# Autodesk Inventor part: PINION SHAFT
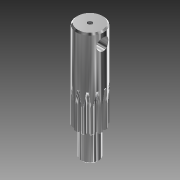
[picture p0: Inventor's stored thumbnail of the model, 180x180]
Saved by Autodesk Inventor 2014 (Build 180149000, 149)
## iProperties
Shininess: 64.0
Length Units: 11269
Angle Units: 11279
Time Units: 11290
Mass Units: 11283
Length Display Precision: 3
Angle Display Precision: 2
Compacted: True
Part Number: PINION SHAFT
Document SubType Name: Modeling
Created: 2003-10
Designer: Autodesk, Inc.
Manufacturer: Standard
Standards Organization: Custom
Mass: 506.446 g
Surface Area: 152.229 cm^2
Volume: 64.5977 cm^3
Density: 7.84 g/cm^3
Material: Steel, High Strength Low Alloy
Appearance: Chrome - Polished
Density: 0.0
Volumn: 0.0
Area: 0.0
PropertySet Name: Model Information
Control State: 0
Master: False
Checked Out: False
Author: Autodesk, Inc.
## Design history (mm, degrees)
sketch "Sketch1" dims "d4" = 6.7945 (= Big_R), "d5" = 5.54567 (= 2 x little_r)
  geometry: L1 (0, 12.7)-(5.815, 12.7); L2 (5.815, 12.7)-(5.815, 14.817); L3 (5.815, 14.817)-(0, 14.817); L4 (0, 14.817)-(0, 12.7); L5 (-8.163, 9.729)-(5.815, 14.817); L6 (0, 0)-(0, 10.251); L7 (0, 11.934)-(0, 12.7); L8 (0, 11.934)-(0, 10.251); L9 (-0.191, 11.933)-(-0.184, 10.731); L10 (-0.181, 10.249)-(0, 0); L11 (0, 0)-(1.934, 14.69); L12 (0, 0)-(-1.338, 10.163); L13 (0, 0)-(3.923, 9.471); L14 (3.273, 11.477)-(2.955, 10.318); L15 (-0.181, 10.249)-(-0.184, 10.731); A1 r 12.7 centre (0, 0) between (0, 12.7) and (-8.163, 9.729); A2 r 14.817 centre (0, 0) between (0, 14.817) and (1.934, 14.69); A3 r 11.934 centre (0, 0) between (0, 11.934) and (6.294, 10.14); A4 r 10.251 centre (0, 0) between (0, 10.251) and (-0.181, 10.249); A5 r 6.795 centre (6.294, 10.14) between (1.365, 14.817) and (0, 12.7); A6 r 2.773 centre (2.568, 11.654) between (0, 12.7) and (-0.191, 11.933); A7 r 10.251 centre (0, 0) between (-0.651, 10.23) and (-1.338, 10.163); A8 r 0.498 centre (-0.682, 10.728) between (-0.651, 10.23) and (-0.184, 10.731); A9 r 10.251 centre (0, 0) between (3.923, 9.471) and (3.276, 9.713); A10 r 0.498 centre (3.435, 10.186) between (2.955, 10.318) and (3.276, 9.713); A11 r 2.773 centre (0.536, 11.922) between (3.273, 11.477) and (3.287, 12.267); A12 r 6.795 centre (-3.455, 11.423) between (3.287, 12.267) and (2.516, 14.665); A13 r 14.879 centre (0, 0) between (2.516, 14.665) and (1.365, 14.817); 2 further points
  constraints: 30 point on circle, 29 end point, 13 centre point, 9 coincident, 9 symmetric about line, 4 tangent, 3 collinear, 3 point on line, 2 parallel, 2 vertical, 1 horizontal, 1 perpendicular, 12 other
  dimensions: "d0" = 25.4 diameter of A1 (= Pitch_Diameter); "d1" = 2.11667 distance of L1.end L2.end (= Addendum); "d2" = 20 deg angle of L1 L5 (= Tooth_Form); "d3" = 4.56565 distance of L6.end L3.end (= Whole_Depth); "d6" = 7.5 deg angle of L11 L6 (= mirror_angle); "d7" = 7.5 deg angle of L12 L6 (= mirror_angle); "d8" = 0.49848 radius of A8 (= Root_Fillet)
extrude "Extrusion1" new body sketch "Sketch1" distance "d9" = 25.4; taper "d10" = 0 deg
pattern_circular "Circular Pattern1" dims angle "d13" = 360 deg
sketch "Sketch2"
  geometry: C1 r 14.879 at (0, 0); 1 further point
  constraints: 1 centre point, 1 coincident
  dimensions: "d14" = 29.758 diameter of C1
extrude "Extrusion2" join sketch "Sketch2" distance "d15" = 71.4502; taper "d16" = 0 deg
sketch "Sketch3"
  geometry: C1 r 9.5 at (0, 0); 1 further point
  constraints: 1 centre point, 1 coincident
  dimensions: "d17" = 18.9992 diameter of C1
extrude "Extrusion3" join sketch "Sketch3" distance "d18" = 30.1498; taper "d19" = 0 deg
chamfer "Chamfer1" distance "d20" = 1.5875; stored, may be unused: second distance "d21" = 2, angle "d67" = 45 deg
chamfer "Chamfer2" distance "d22" = 1.5875; stored, may be unused: second distance "d23" = 2, angle "d68" = 45 deg
workplane "Work Plane2"
sketch "Sketch4"
  geometry: L1 (-13.292, 96.85)-(13.292, 96.85) reference; L2 (0, 96.85)-(0, 65.832); C1 r 6.54 at (0, 84.15)
  constraints: 2 end point, 1 centre point, 1 midpoint, 1 perpendicular, 1 point on line
  dimensions: "d26" = 13.081 diameter of C1; "d27" = 12.7 distance from line of L1 C1.centre
extrude "Extrusion4" cut sketch "Sketch4" distance "d28" = 50.8; taper "d29" = 0 deg
workplane "Work Plane3"
sketch "Sketch10"
  geometry: L1 (-5.206, 9.385)-(-5.801, 10.429) reference; L2 (-3.273, 11.477)-(-2.955, 10.318) reference; L3 (-5.801, 10.429)-(-5.206, 9.385); L4 (-2.955, 10.318)-(-3.273, 11.477); L5 (-30.301, 30.745)-(3.482, 44.738); L6 (-8.59, 12.149)-(-2.517, 14.665); L7 (0.184, 10.731)-(0.191, 11.933) reference; L8 (2.904, 11.575)-(2.6, 10.413) reference; L9 (0.191, 11.933)-(0.184, 10.731); L10 (2.904, 11.575)-(2.6, 10.413); L11 (5.524, 9.201)-(6.131, 10.239) reference; L12 (8.303, 8.572)-(7.458, 7.718) reference; L13 (5.524, 9.201)-(6.131, 10.239); L14 (7.458, 7.718)-(8.303, 8.572); L15 (9.385, 5.206)-(10.429, 5.801) reference; L16 (11.477, 3.273)-(10.318, 2.955) reference; L17 (9.385, 5.206)-(10.429, 5.801); L18 (11.477, 3.273)-(10.318, 2.955); A1 r 6.795 centre (3.455, 11.423) between (-2.517, 14.665) and (-3.287, 12.267) reference; A2 r 14.879 centre (0, 0) between (-2.517, 14.665) and (-8.59, 12.149) reference; A3 r 6.795 centre (-10.52, 5.634) between (-6.35, 10.999) and (-8.59, 12.149) reference; A4 r 2.773 centre (-8.051, 8.809) between (-5.801, 10.429) and (-6.35, 10.999) reference; A5 r 0.498 centre (-4.773, 9.632) between (-5.206, 9.385) and (-4.552, 9.185) reference; A6 r 10.251 centre (0, 0) between (-3.276, 9.713) and (-4.552, 9.185) reference; A7 r 0.498 centre (-3.435, 10.186) between (-3.276, 9.713) and (-2.955, 10.318) reference; A8 r 2.773 centre (-0.536, 11.922) between (-3.287, 12.267) and (-3.273, 11.477) reference; A9 r 14.879 centre (0, 0) between (-2.517, 14.665) and (-8.59, 12.149); A10 r 6.795 centre (-10.52, 5.634) between (-6.35, 10.999) and (-8.59, 12.149); A11 r 2.773 centre (-8.051, 8.809) between (-5.801, 10.429) and (-6.35, 10.999); A12 r 0.498 centre (-4.773, 9.632) between (-5.206, 9.385) and (-4.552, 9.185); A13 r 10.251 centre (0, 0) between (-3.276, 9.713) and (-4.552, 9.185); A14 r 6.795 centre (3.455, 11.423) between (-2.517, 14.665) and (-3.287, 12.267); A15 r 2.773 centre (-0.536, 11.922) between (-3.287, 12.267) and (-3.273, 11.477); A16 r 0.498 centre (-3.435, 10.186) between (-3.276, 9.713) and (-2.955, 10.318); A17 r 10.251 centre (0, 0) between (-3.276, 9.713) and (-4.552, 9.185) reference; A18 r 6.795 centre (8.704, 8.165) between (5.153, 13.958) and (3.287, 12.267) reference; A19 r 14.879 centre (0, 0) between (5.153, 13.958) and (-1.365, 14.816) reference; A20 r 6.795 centre (-6.294, 10.14) between (0, 12.7) and (-1.365, 14.816) reference; A21 r 2.773 centre (-2.568, 11.654) between (0.191, 11.933) and (0, 12.7) reference; A22 r 0.498 centre (0.682, 10.728) between (0.184, 10.731) and (0.651, 10.23) reference; A23 r 10.251 centre (0, 0) between (2.019, 10.05) and (0.651, 10.23) reference; A24 r 0.498 centre (2.118, 10.539) between (2.019, 10.05) and (2.6, 10.413) reference; A25 r 2.773 centre (5.497, 10.593) between (3.287, 12.267) and (2.904, 11.575) reference; A26 r 6.795 centre (-6.294, 10.14) between (0, 12.7) and (-1.365, 14.816); A27 r 2.773 centre (-2.568, 11.654) between (0.191, 11.933) and (0, 12.7); A28 r 0.498 centre (0.682, 10.728) between (0.184, 10.731) and (0.651, 10.23); A29 r 0.498 centre (2.118, 10.539) between (2.019, 10.05) and (2.6, 10.413); A30 r 2.773 centre (5.497, 10.593) between (3.287, 12.267) and (2.904, 11.575); A31 r 6.795 centre (8.704, 8.165) between (5.153, 13.958) and (3.287, 12.267); A32 r 14.879 centre (0, 0) between (5.153, 13.958) and (-1.365, 14.816); A33 r 10.251 centre (0, 0) between (2.019, 10.05) and (0.651, 10.23); A34 r 6.795 centre (11.62, 2.72) between (11.442, 9.512) and (8.98, 8.98) reference; A35 r 14.879 centre (0, 0) between (11.442, 9.512) and (6.226, 13.514) reference; A36 r 6.795 centre (-0.381, 11.928) between (6.35, 10.999) and (6.226, 13.514) reference; A37 r 2.773 centre (3.603, 11.377) between (6.131, 10.239) and (6.35, 10.999) reference; A38 r 0.498 centre (5.955, 8.949) between (5.524, 9.201) and (5.679, 8.534) reference; A39 r 10.251 centre (0, 0) between (6.774, 7.694) and (5.679, 8.534) reference; A40 r 0.498 centre (7.103, 8.068) between (6.774, 7.694) and (7.458, 7.718) reference; A41 r 2.773 centre (10.057, 6.425) between (8.98, 8.98) and (8.303, 8.572) reference; A42 r 14.879 centre (0, 0) between (11.442, 9.512) and (6.226, 13.514); A43 r 6.795 centre (-0.381, 11.928) between (6.35, 10.999) and (6.226, 13.514); A44 r 2.773 centre (3.603, 11.377) between (6.131, 10.239) and (6.35, 10.999); A45 r 0.498 centre (5.955, 8.949) between (5.524, 9.201) and (5.679, 8.534); A46 r 0.498 centre (7.103, 8.068) between (6.774, 7.694) and (7.458, 7.718); A47 r 2.773 centre (10.057, 6.425) between (8.98, 8.98) and (8.303, 8.572); A48 r 6.795 centre (11.62, 2.72) between (11.442, 9.512) and (8.98, 8.98); A49 r 10.251 centre (0, 0) between (6.774, 7.694) and (5.679, 8.534); A50 r 6.795 centre (11.423, -3.455) between (14.665, 2.517) and (12.267, 3.287) reference; A51 r 14.879 centre (0, 0) between (14.665, 2.517) and (12.149, 8.59) reference; A52 r 6.795 centre (5.634, 10.52) between (10.999, 6.35) and (12.149, 8.59) reference; A53 r 2.773 centre (8.809, 8.051) between (10.429, 5.801) and (10.999, 6.35) reference; A54 r 0.498 centre (9.632, 4.773) between (9.385, 5.206) and (9.185, 4.552) reference; A55 r 10.251 centre (0, 0) between (9.713, 3.276) and (9.185, 4.552) reference; A56 r 0.498 centre (10.186, 3.435) between (9.713, 3.276) and (10.318, 2.955) reference; A57 r 2.773 centre (11.922, 0.536) between (12.267, 3.287) and (11.477, 3.273) reference; A58 r 10.251 centre (0, 0) between (9.713, 3.276) and (9.185, 4.552); A59 r 0.498 centre (9.632, 4.773) between (9.385, 5.206) and (9.185, 4.552); A60 r 0.498 centre (10.186, 3.435) between (9.713, 3.276) and (10.318, 2.955); A61 r 2.773 centre (11.922, 0.536) between (12.267, 3.287) and (11.477, 3.273); A62 r 2.773 centre (8.809, 8.051) between (10.429, 5.801) and (10.999, 6.35); A63 r 6.795 centre (5.634, 10.52) between (10.999, 6.35) and (12.149, 8.59); A64 r 6.794 centre (11.423, -3.455) between (14.665, 2.517) and (12.267, 3.287)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
  constraints: 66 point on circle, 32 centre point, 30 concentric, 27 tangent, 20 end point, 8 collinear, 1 parallel
  dimensions: "d32" = 40 distance from line of L5 A17.centre
revolve "Revolution1" sketch "Sketch10" stored, may be unused: angle "d33" = 90 deg
sketch "Sketch11"
  geometry: L1 (0.184, 10.731)-(0.191, 11.933) reference; L2 (2.904, 11.575)-(2.6, 10.413) reference; L3 (0.184, 10.731)-(0.191, 11.933); L4 (2.6, 10.413)-(2.904, 11.575); L5 (-8.56, 41.472)-(25.088, 37.042); L6 (-1.365, 14.816)-(5.153, 13.958); C1 r 7.912 at (0, 0) reference; A1 r 6.795 centre (8.704, 8.165) between (5.153, 13.958) and (3.287, 12.267) reference; A2 r 14.879 centre (0, 0) between (5.153, 13.958) and (-1.365, 14.816) reference; A3 r 6.795 centre (-6.294, 10.14) between (0, 12.7) and (-1.365, 14.816) reference; A4 r 2.773 centre (-2.568, 11.654) between (0.191, 11.933) and (0, 12.7) reference; A5 r 0.498 centre (0.682, 10.728) between (0.184, 10.731) and (0.651, 10.23) reference; A6 r 10.251 centre (0, 0) between (2.019, 10.05) and (0.651, 10.23) reference; A7 r 0.498 centre (2.118, 10.539) between (2.019, 10.05) and (2.6, 10.413) reference; A8 r 2.773 centre (5.497, 10.593) between (3.287, 12.267) and (2.904, 11.575) reference; A9 r 14.879 centre (0, 0) between (5.153, 13.958) and (-1.365, 14.816); A10 r 6.795 centre (-6.294, 10.14) between (0, 12.7) and (-1.365, 14.816); A11 r 2.773 centre (-2.568, 11.654) between (0.191, 11.933) and (0, 12.7); A12 r 0.498 centre (0.682, 10.728) between (0.184, 10.731) and (0.651, 10.23); A13 r 10.251 centre (0, 0) between (2.019, 10.05) and (0.651, 10.23); A14 r 6.795 centre (8.704, 8.165) between (5.153, 13.958) and (3.287, 12.267); A15 r 2.773 centre (5.497, 10.593) between (3.287, 12.267) and (2.904, 11.575); A16 r 0.498 centre (2.118, 10.539) between (2.019, 10.05) and (2.6, 10.413)
  constraints: 16 point on circle, 8 centre point, 8 end point, 8 tangent, 6 concentric, 2 collinear, 1 parallel
  dimensions: "d35" = 40 distance from line of C1.centre L5
revolve "Revolution2" sketch "Sketch11" stored, may be unused: angle "d36" = 90 deg
sketch "Sketch12"
  geometry: L1 (5.524, 9.201)-(6.131, 10.239) reference; L2 (8.303, 8.572)-(7.458, 7.718) reference; L3 (8.303, 8.572)-(7.458, 7.718); L4 (5.524, 9.201)-(6.131, 10.239); L5 (37.465, 21.671)-(7.155, 44.928); L6 (11.442, 9.512)-(6.226, 13.514); C1 r 7.912 at (0, 0) reference; A1 r 6.795 centre (11.62, 2.72) between (11.442, 9.512) and (8.98, 8.98) reference; A2 r 14.879 centre (0, 0) between (11.442, 9.512) and (6.226, 13.514) reference; A3 r 6.795 centre (-0.381, 11.928) between (6.35, 10.999) and (6.226, 13.514) reference; A4 r 2.773 centre (3.603, 11.377) between (6.131, 10.239) and (6.35, 10.999) reference; A5 r 0.498 centre (5.955, 8.949) between (5.524, 9.201) and (5.679, 8.534) reference; A6 r 10.251 centre (0, 0) between (6.774, 7.694) and (5.679, 8.534) reference; A7 r 0.498 centre (7.103, 8.068) between (6.774, 7.694) and (7.458, 7.718) reference; A8 r 2.773 centre (10.057, 6.425) between (8.98, 8.98) and (8.303, 8.572) reference; A9 r 14.879 centre (0, 0) between (11.442, 9.512) and (6.226, 13.514); A10 r 0.498 centre (5.955, 8.949) between (5.524, 9.201) and (5.679, 8.534); A11 r 6.795 centre (-0.381, 11.928) between (6.35, 10.999) and (6.226, 13.514); A12 r 2.773 centre (3.603, 11.377) between (6.131, 10.239) and (6.35, 10.999); A13 r 0.498 centre (7.103, 8.068) between (6.774, 7.694) and (7.458, 7.718); A14 r 2.773 centre (10.057, 6.425) between (8.98, 8.98) and (8.303, 8.572); A15 r 6.795 centre (11.62, 2.72) between (11.442, 9.512) and (8.98, 8.98); A16 r 10.251 centre (0, 0) between (6.774, 7.694) and (5.679, 8.534)
  constraints: 16 point on circle, 8 centre point, 8 end point, 7 concentric, 7 tangent, 2 collinear, 1 parallel
  dimensions: "d37" = 40 distance from line of C1.centre L5
revolve "Revolution3" sketch "Sketch12" stored, may be unused: angle "d38" = 90 deg
sketch "Sketch13"
  geometry: L1 (9.385, 5.206)-(10.429, 5.801) reference; L2 (11.477, 3.273)-(10.318, 2.955) reference; L3 (9.385, 5.206)-(10.429, 5.801); L4 (10.318, 2.955)-(11.477, 3.273); L5 (14.665, 2.517)-(12.149, 8.59); L6 (43.302, -0.015)-(26.182, 41.316); C1 r 7.912 at (0, 0) reference; A1 r 6.795 centre (11.423, -3.455) between (14.665, 2.517) and (12.267, 3.287) reference; A2 r 14.879 centre (0, 0) between (14.665, 2.517) and (12.149, 8.59) reference; A3 r 6.795 centre (5.634, 10.52) between (10.999, 6.35) and (12.149, 8.59) reference; A4 r 2.773 centre (8.809, 8.051) between (10.429, 5.801) and (10.999, 6.35) reference; A5 r 0.498 centre (9.632, 4.773) between (9.385, 5.206) and (9.185, 4.552) reference; A6 r 10.251 centre (0, 0) between (9.713, 3.276) and (9.185, 4.552) reference; A7 r 0.498 centre (10.186, 3.435) between (9.713, 3.276) and (10.318, 2.955) reference; A8 r 2.773 centre (11.922, 0.536) between (12.267, 3.287) and (11.477, 3.273) reference; A9 r 6.795 centre (5.634, 10.52) between (10.999, 6.35) and (12.149, 8.59); A10 r 2.773 centre (8.809, 8.051) between (10.429, 5.801) and (10.999, 6.35); A11 r 0.498 centre (9.632, 4.773) between (9.385, 5.206) and (9.185, 4.552); A12 r 0.498 centre (10.186, 3.435) between (9.713, 3.276) and (10.318, 2.955); A13 r 2.773 centre (11.922, 0.536) between (12.267, 3.287) and (11.477, 3.273); A14 r 10.251 centre (0, 0) between (9.713, 3.276) and (9.185, 4.552); A15 r 6.795 centre (11.423, -3.455) between (14.665, 2.517) and (12.267, 3.287); A16 r 14.879 centre (0, 0) between (14.665, 2.517) and (12.149, 8.59)
  constraints: 16 point on circle, 8 centre point, 8 concentric, 8 end point, 2 collinear, 2 tangent, 1 parallel
  dimensions: "d39" = 40 distance from line of C1.centre L6
  node "Projected Loop8"
sketch "Sketch14"
  geometry: L1 (-9.201, 5.524)-(-10.239, 6.131) reference; L2 (-8.572, 8.303)-(-7.718, 7.458) reference; L3 (-9.201, 5.524)-(-10.239, 6.131); L4 (-7.718, 7.458)-(-8.572, 8.303); L5 (-13.514, 6.226)-(-9.512, 11.442); L6 (-43.85, 8.561)-(-20.3, 39.252); C1 r 7.912 at (0, 0) reference; A1 r 6.795 centre (-11.928, -0.381) between (-10.999, 6.35) and (-13.514, 6.226) reference; A2 r 2.773 centre (-11.377, 3.603) between (-10.239, 6.131) and (-10.999, 6.35) reference; A3 r 0.498 centre (-8.949, 5.955) between (-9.201, 5.524) and (-8.534, 5.679) reference; A4 r 10.251 centre (0, 0) between (-7.694, 6.774) and (-8.534, 5.679) reference; A5 r 0.498 centre (-8.068, 7.103) between (-7.694, 6.774) and (-7.718, 7.458) reference; A6 r 2.773 centre (-6.425, 10.057) between (-8.98, 8.98) and (-8.572, 8.303) reference; A7 r 6.795 centre (-2.72, 11.62) between (-9.512, 11.442) and (-8.98, 8.98) reference; A8 r 14.879 centre (0, 0) between (-9.512, 11.442) and (-13.514, 6.226) reference; A9 r 14.879 centre (0, 0) between (-9.512, 11.442) and (-13.514, 6.226); A10 r 0.498 centre (-8.949, 5.955) between (-9.201, 5.524) and (-8.534, 5.679); A11 r 2.773 centre (-11.377, 3.603) between (-10.239, 6.131) and (-10.999, 6.35); A12 r 6.795 centre (-11.928, -0.381) between (-10.999, 6.35) and (-13.514, 6.226); A13 r 6.795 centre (-2.72, 11.62) between (-9.512, 11.442) and (-8.98, 8.98); A14 r 2.773 centre (-6.425, 10.057) between (-8.98, 8.98) and (-8.572, 8.303); A15 r 10.251 centre (0, 0) between (-7.694, 6.774) and (-8.534, 5.679); A16 r 0.498 centre (-8.068, 7.103) between (-7.694, 6.774) and (-7.718, 7.458)
  constraints: 17 point on circle, 8 centre point, 8 end point, 8 tangent, 6 concentric, 2 collinear, 1 parallel
  dimensions: "d40" = 40 distance from line of C1.centre L6
revolve "Revolution5" sketch "Sketch14" stored, may be unused: angle "d42" = 90 deg
revolve "Revolution6" stored, may be unused: angle "d43" = 90 deg
sketch "Sketch15"
  geometry: L1 (10.731, -0.184)-(11.933, -0.191) reference; L2 (11.575, -2.904)-(10.413, -2.6) reference; L3 (10.731, -0.184)-(11.933, -0.191); L4 (10.413, -2.6)-(11.575, -2.904); L5 (13.958, -5.153)-(14.816, 1.365); L6 (42.416, 15.732)-(37.273, -23.332); C1 r 7.912 at (0, 0) reference; A1 r 6.795 centre (8.165, -8.704) between (13.958, -5.153) and (12.267, -3.287) reference; A2 r 14.879 centre (0, 0) between (13.958, -5.153) and (14.816, 1.365) reference; A3 r 6.795 centre (10.14, 6.294) between (12.7, 0) and (14.816, 1.365) reference; A4 r 2.773 centre (11.654, 2.568) between (11.933, -0.191) and (12.7, 0) reference; A5 r 0.498 centre (10.728, -0.682) between (10.731, -0.184) and (10.23, -0.651) reference; A6 r 10.251 centre (0, 0) between (10.05, -2.019) and (10.23, -0.651) reference; A7 r 0.498 centre (10.539, -2.118) between (10.05, -2.019) and (10.413, -2.6) reference; A8 r 2.773 centre (10.593, -5.497) between (12.267, -3.287) and (11.575, -2.904) reference; A9 r 14.879 centre (0, 0) between (13.958, -5.153) and (14.816, 1.365); A10 r 6.795 centre (10.14, 6.294) between (12.7, 0) and (14.816, 1.365); A11 r 2.773 centre (11.654, 2.568) between (11.933, -0.191) and (12.7, 0); A12 r 0.498 centre (10.728, -0.682) between (10.731, -0.184) and (10.23, -0.651); A13 r 10.251 centre (0, 0) between (10.05, -2.019) and (10.23, -0.651); A14 r 0.498 centre (10.539, -2.118) between (10.05, -2.019) and (10.413, -2.6); A15 r 2.773 centre (10.593, -5.497) between (12.267, -3.287) and (11.575, -2.904); A16 r 6.795 centre (8.165, -8.704) between (13.958, -5.153) and (12.267, -3.287)
  constraints: 16 point on circle, 8 centre point, 8 concentric, 8 end point, 5 tangent, 2 collinear, 1 parallel
  dimensions: "d44" = 40 distance from line of C1.centre L6
revolve "Revolution7" sketch "Sketch15" stored, may be unused: angle "d45" = 90 deg
sketch "Sketch16"
  geometry: L1 (9.201, -5.524)-(10.239, -6.131) reference; L2 (8.572, -8.303)-(7.718, -7.458) reference; L3 (9.201, -5.524)-(10.239, -6.131); L4 (7.718, -7.458)-(8.572, -8.303); L5 (9.512, -11.442)-(13.514, -6.226); L6 (22.205, -36.769)-(41.695, -11.369); C1 r 7.912 at (0, 0) reference; A1 r 6.795 centre (2.72, -11.62) between (9.512, -11.442) and (8.98, -8.98) reference; A2 r 14.879 centre (0, 0) between (9.512, -11.442) and (13.514, -6.226) reference; A3 r 6.795 centre (11.928, 0.381) between (10.999, -6.35) and (13.514, -6.226) reference; A4 r 2.773 centre (11.377, -3.603) between (10.239, -6.131) and (10.999, -6.35) reference; A5 r 0.498 centre (8.949, -5.955) between (9.201, -5.524) and (8.534, -5.679) reference; A6 r 10.251 centre (0, 0) between (7.694, -6.774) and (8.534, -5.679) reference; A7 r 0.498 centre (8.068, -7.103) between (7.694, -6.774) and (7.718, -7.458) reference; A8 r 2.773 centre (6.425, -10.057) between (8.98, -8.98) and (8.572, -8.303) reference; A9 r 14.879 centre (0, 0) between (9.512, -11.442) and (13.514, -6.226); A10 r 6.795 centre (11.928, 0.381) between (10.999, -6.35) and (13.514, -6.226); A11 r 2.773 centre (11.377, -3.603) between (10.239, -6.131) and (10.999, -6.35); A12 r 0.498 centre (8.949, -5.955) between (9.201, -5.524) and (8.534, -5.679); A13 r 0.498 centre (8.068, -7.103) between (7.694, -6.774) and (7.718, -7.458); A14 r 2.773 centre (6.425, -10.057) between (8.98, -8.98) and (8.572, -8.303); A15 r 6.795 centre (2.72, -11.62) between (9.512, -11.442) and (8.98, -8.98); A16 r 10.251 centre (0, 0) between (7.694, -6.774) and (8.534, -5.679)
  constraints: 18 point on circle, 9 tangent, 8 centre point, 8 end point, 6 concentric, 2 collinear, 1 parallel
  dimensions: "d51" = 40 distance from line of C1.centre L6
revolve "Revolution8" sketch "Sketch16" stored, may be unused: angle "d48" = 90 deg
sketch "Sketch17"
  geometry: L1 (5.206, -9.385)-(5.801, -10.429) reference; L2 (3.273, -11.477)-(2.955, -10.318) reference; L3 (5.206, -9.385)-(5.801, -10.429); L4 (2.955, -10.318)-(3.273, -11.477); L5 (8.59, -12.149)-(2.517, -14.665); L6 (-1.988, -44.119)-(32.429, -29.863); C1 r 7.912 at (0, 0) reference; A1 r 6.795 centre (10.52, -5.634) between (6.35, -10.999) and (8.59, -12.149) reference; A2 r 2.773 centre (8.051, -8.809) between (5.801, -10.429) and (6.35, -10.999) reference; A3 r 0.498 centre (4.773, -9.632) between (5.206, -9.385) and (4.552, -9.185) reference; A4 r 10.251 centre (0, 0) between (3.276, -9.713) and (4.552, -9.185) reference; A5 r 0.498 centre (3.435, -10.186) between (3.276, -9.713) and (2.955, -10.318) reference; A6 r 2.773 centre (0.536, -11.922) between (3.287, -12.267) and (3.273, -11.477) reference; A7 r 6.795 centre (-3.455, -11.423) between (2.517, -14.665) and (3.287, -12.267) reference; A8 r 14.879 centre (0, 0) between (2.517, -14.665) and (8.59, -12.149) reference; A9 r 14.879 centre (0, 0) between (2.517, -14.665) and (8.59, -12.149); A10 r 6.795 centre (-3.455, -11.423) between (2.517, -14.665) and (3.287, -12.267); A11 r 2.773 centre (0.536, -11.922) between (3.287, -12.267) and (3.273, -11.477); A12 r 0.498 centre (3.435, -10.186) between (3.276, -9.713) and (2.955, -10.318); A13 r 0.498 centre (4.773, -9.632) between (5.206, -9.385) and (4.552, -9.185); A14 r 6.795 centre (10.52, -5.634) between (6.35, -10.999) and (8.59, -12.149); A15 r 2.773 centre (8.051, -8.809) between (5.801, -10.429) and (6.35, -10.999); A16 r 10.251 centre (0, 0) between (3.276, -9.713) and (4.552, -9.185)
  constraints: 17 point on circle, 8 centre point, 8 end point, 7 concentric, 5 tangent, 2 collinear, 1 parallel
  dimensions: "d49" = 40 distance from line of C1.centre L6
revolve "Revolution9" sketch "Sketch17" stored, may be unused: angle "d50" = 90 deg
sketch "Sketch18"
  geometry: L1 (-0.184, -10.731)-(-0.191, -11.933) reference; L2 (-2.904, -11.575)-(-2.6, -10.413) reference; L3 (-0.184, -10.731)-(-0.191, -11.933); L4 (-2.6, -10.413)-(-2.904, -11.575); L5 (-5.153, -13.958)-(1.365, -14.816); L6 (18.309, -42.756)-(-25.099, -37.041); C1 r 7.912 at (0, 0) reference; A1 r 6.795 centre (6.294, -10.14) between (0, -12.7) and (1.365, -14.816) reference; A2 r 2.773 centre (2.568, -11.654) between (-0.191, -11.933) and (0, -12.7) reference; A3 r 0.498 centre (-0.682, -10.728) between (-0.184, -10.731) and (-0.651, -10.23) reference; A4 r 10.251 centre (0, 0) between (-2.019, -10.05) and (-0.651, -10.23) reference; A5 r 0.498 centre (-2.118, -10.539) between (-2.019, -10.05) and (-2.6, -10.413) reference; A6 r 2.773 centre (-5.497, -10.593) between (-3.287, -12.267) and (-2.904, -11.575) reference; A7 r 6.795 centre (-8.704, -8.165) between (-5.153, -13.958) and (-3.287, -12.267) reference; A8 r 14.879 centre (0, 0) between (-5.153, -13.958) and (1.365, -14.816) reference; A9 r 14.879 centre (0, 0) between (-5.153, -13.958) and (1.365, -14.816); A10 r 6.795 centre (6.294, -10.14) between (0, -12.7) and (1.365, -14.816); A11 r 0.498 centre (-0.682, -10.728) between (-0.184, -10.731) and (-0.651, -10.23); A12 r 2.773 centre (2.568, -11.654) between (-0.191, -11.933) and (0, -12.7); A13 r 6.795 centre (-8.704, -8.165) between (-5.153, -13.958) and (-3.287, -12.267); A14 r 2.773 centre (-5.497, -10.593) between (-3.287, -12.267) and (-2.904, -11.575); A15 r 0.498 centre (-2.118, -10.539) between (-2.019, -10.05) and (-2.6, -10.413); A16 r 10.251 centre (0, 0) between (-2.019, -10.05) and (-0.651, -10.23)
  constraints: 16 point on circle, 9 tangent, 8 centre point, 8 end point, 6 concentric, 2 collinear, 1 parallel
  dimensions: "d52" = 40 distance from line of L6 C1.centre
revolve "Revolution10" sketch "Sketch18" stored, may be unused: angle "d53" = 90 deg
sketch "Sketch19"
  geometry: L1 (-5.524, -9.201)-(-6.131, -10.239) reference; L2 (-8.303, -8.572)-(-7.458, -7.718) reference; L3 (-5.524, -9.201)-(-6.131, -10.239); L4 (-7.458, -7.718)-(-8.303, -8.572); L5 (-11.442, -9.512)-(-6.226, -13.514); L6 (-14.257, -39.479)-(-36.918, -22.091); C1 r 7.912 at (0, 0) reference; A1 r 6.795 centre (0.381, -11.928) between (-6.35, -10.999) and (-6.226, -13.514) reference; A2 r 2.773 centre (-3.603, -11.377) between (-6.131, -10.239) and (-6.35, -10.999) reference; A3 r 0.498 centre (-5.955, -8.949) between (-5.524, -9.201) and (-5.679, -8.534) reference; A4 r 10.251 centre (0, 0) between (-6.774, -7.694) and (-5.679, -8.534) reference; A5 r 0.498 centre (-7.103, -8.068) between (-6.774, -7.694) and (-7.458, -7.718) reference; A6 r 2.773 centre (-10.057, -6.425) between (-8.98, -8.98) and (-8.303, -8.572) reference; A7 r 6.795 centre (-11.62, -2.72) between (-11.442, -9.512) and (-8.98, -8.98) reference; A8 r 14.879 centre (0, 0) between (-11.442, -9.512) and (-6.226, -13.514) reference; A9 r 14.879 centre (0, 0) between (-11.442, -9.512) and (-6.226, -13.514); A10 r 6.795 centre (0.381, -11.928) between (-6.35, -10.999) and (-6.226, -13.514); A11 r 0.498 centre (-5.955, -8.949) between (-5.524, -9.201) and (-5.679, -8.534); A12 r 0.498 centre (-7.103, -8.068) between (-6.774, -7.694) and (-7.458, -7.718); A13 r 6.795 centre (-11.62, -2.72) between (-11.442, -9.512) and (-8.98, -8.98); A14 r 10.251 centre (0, 0) between (-6.774, -7.694) and (-5.679, -8.534); A15 r 2.773 centre (-10.057, -6.425) between (-8.98, -8.98) and (-8.303, -8.572); A16 r 2.773 centre (-3.603, -11.377) between (-6.131, -10.239) and (-6.35, -10.999)
  constraints: 16 point on circle, 11 tangent, 8 centre point, 8 end point, 5 concentric, 2 collinear, 1 parallel
  dimensions: "d54" = 40 distance from line of C1.centre L6
revolve "Revolution11" sketch "Sketch19" stored, may be unused: angle "d55" = 90 deg
sketch "Sketch20"
  geometry: L1 (-9.385, -5.206)-(-10.429, -5.801) reference; L2 (-11.477, -3.273)-(-10.318, -2.955) reference; L3 (-9.385, -5.206)-(-10.429, -5.801); L4 (-10.318, -2.955)-(-11.477, -3.273); L5 (-14.665, -2.517)-(-12.149, -8.59); L6 (-31.542, -28.377)-(-43.268, -0.067); C1 r 7.912 at (0, 0) reference; A1 r 6.795 centre (-5.634, -10.52) between (-10.999, -6.35) and (-12.149, -8.59) reference; A2 r 2.773 centre (-8.809, -8.051) between (-10.429, -5.801) and (-10.999, -6.35) reference; A3 r 0.498 centre (-9.632, -4.773) between (-9.385, -5.206) and (-9.185, -4.552) reference; A4 r 10.251 centre (0, 0) between (-9.713, -3.276) and (-9.185, -4.552) reference; A5 r 0.498 centre (-10.186, -3.435) between (-9.713, -3.276) and (-10.318, -2.955) reference; A6 r 2.773 centre (-11.922, -0.536) between (-12.267, -3.287) and (-11.477, -3.273) reference; A7 r 6.795 centre (-11.423, 3.455) between (-14.665, -2.517) and (-12.267, -3.287) reference; A8 r 14.879 centre (0, 0) between (-14.665, -2.517) and (-12.149, -8.59) reference; A9 r 14.879 centre (0, 0) between (-14.665, -2.517) and (-12.149, -8.59); A10 r 6.795 centre (-11.423, 3.455) between (-14.665, -2.517) and (-12.267, -3.287); A11 r 6.795 centre (-5.634, -10.52) between (-10.999, -6.35) and (-12.149, -8.59); A12 r 0.498 centre (-9.632, -4.773) between (-9.385, -5.206) and (-9.185, -4.552); A13 r 0.498 centre (-10.186, -3.435) between (-9.713, -3.276) and (-10.318, -2.955); A14 r 2.773 centre (-11.922, -0.536) between (-12.267, -3.287) and (-11.477, -3.273); A15 r 2.773 centre (-8.809, -8.051) between (-10.429, -5.801) and (-10.999, -6.35); A16 r 10.251 centre (0, 0) between (-9.713, -3.276) and (-9.185, -4.552)
  constraints: 16 point on circle, 8 centre point, 8 end point, 7 concentric, 7 tangent, 2 collinear, 1 parallel
  dimensions: "d56" = 40 distance from line of C1.centre L6
revolve "Revolution12" sketch "Sketch20" stored, may be unused: angle "d57" = 90 deg
sketch "Sketch21"
  geometry: L1 (-10.731, 0.184)-(-11.933, 0.191) reference; L2 (-11.575, 2.904)-(-10.413, 2.6) reference; L3 (-10.731, 0.184)-(-11.933, 0.191); L4 (-10.413, 2.6)-(-11.575, 2.904); L5 (-13.958, 5.153)-(-14.816, -1.365); L6 (-37.606, 20.805)-(-41.538, -9.057); C1 r 7.912 at (0, 0) reference; A1 r 6.795 centre (-10.14, -6.294) between (-12.7, 0) and (-14.816, -1.365) reference; A2 r 2.773 centre (-11.654, -2.568) between (-11.933, 0.191) and (-12.7, 0) reference; A3 r 0.498 centre (-10.728, 0.682) between (-10.731, 0.184) and (-10.23, 0.651) reference; A4 r 10.251 centre (0, 0) between (-10.05, 2.019) and (-10.23, 0.651) reference; A5 r 0.498 centre (-10.539, 2.118) between (-10.05, 2.019) and (-10.413, 2.6) reference; A6 r 2.773 centre (-10.593, 5.497) between (-12.267, 3.287) and (-11.575, 2.904) reference; A7 r 6.795 centre (-8.165, 8.704) between (-13.958, 5.153) and (-12.267, 3.287) reference; A8 r 14.879 centre (0, 0) between (-13.958, 5.153) and (-14.816, -1.365) reference; A9 r 14.879 centre (0, 0) between (-13.958, 5.153) and (-14.816, -1.365); A10 r 6.795 centre (-10.14, -6.294) between (-12.7, 0) and (-14.816, -1.365); A11 r 0.498 centre (-10.728, 0.682) between (-10.731, 0.184) and (-10.23, 0.651); A12 r 0.498 centre (-10.539, 2.118) between (-10.05, 2.019) and (-10.413, 2.6); A13 r 2.773 centre (-10.593, 5.497) between (-12.267, 3.287) and (-11.575, 2.904); A14 r 2.773 centre (-11.654, -2.568) between (-11.933, 0.191) and (-12.7, 0); A15 r 6.795 centre (-8.165, 8.704) between (-13.958, 5.153) and (-12.267, 3.287); A16 r 10.251 centre (0, 0) between (-10.05, 2.019) and (-10.23, 0.651)
  constraints: 16 point on circle, 8 centre point, 8 end point, 6 concentric, 6 tangent, 2 collinear, 1 parallel
  dimensions: "d58" = 40 distance from line of C1.centre L6
revolve "Revolution13" sketch "Sketch21" stored, may be unused: angle "d59" = 90 deg
sketch "Sketch22"
  geometry: C1 r 13.292 at (0, 0) reference; 1 further point
  constraints: 1 coincident
hole "Hole1" sketch "Sketch22" at (0, 0) diameter "d60" = 4.978; stored, may be unused: countersink angle "d64" = 82 deg, drill point angle "d66" = 118 deg; dims "d61" = 6, "d62" = 4, "d63" = 2, "d65" = 8
body "Solid1"
node "Projected Loop2"
node "Projected Loop3"
node "Projected Loop4"
node "Projected Loop5"
node "Projected Loop6"
node "Projected Loop7"
node "Projected Loop9"
node "Projected Loop10"
node "Projected Loop11"
node "Projected Loop12"
node "Projected Loop13"
node "Projected Loop14"
node "Projected Loop15"
node "Projected Loop16"
node "Projected Loop17"
other parameters: "Tooth_Form" = 20 deg [user parameter; used in 1 equation term], "Pitch_Diameter" = 25.4 [user parameter; used in 1 equation term], "Addendum" = 2.11667 [user parameter; used in 1 equation term], "Whole_Depth" = 4.56565 [user parameter; used in 1 equation term], "Big_R" = 6.7945 [user parameter; used in 1 equation term], "little_r" = 2.77283 [user parameter; used in 1 equation term], "Root_Fillet" = 0.49848 [user parameter; used in 1 equation term], "mirror_angle" = 7.5 deg [user parameter; used in 2 equation terms], "d25" = 16.75
